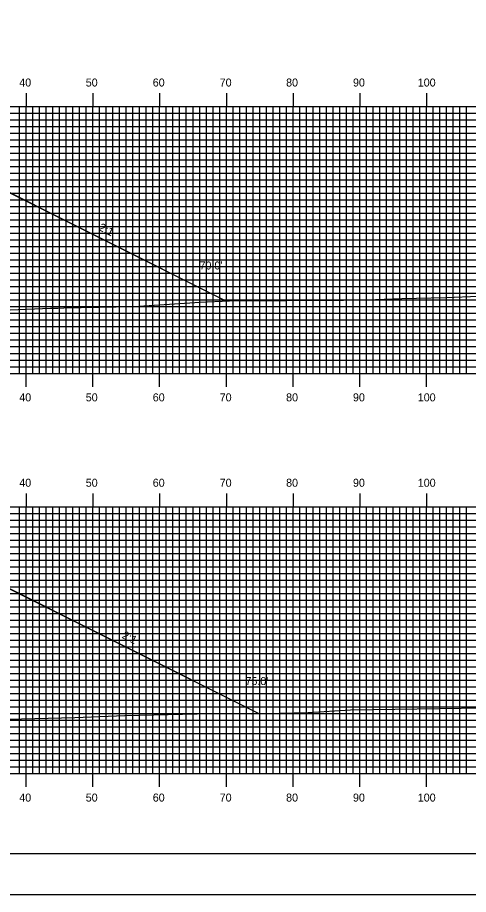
# Model space of a CAD drawing. Extents: x 1759823 to 1760167, y 442591 to 442811.
# Drawn here: x 1760027.9 to 1760095.5, y 442590.5 to 442722 of the extents above; entities that cross this region are included whole.
import ezdxf

# ---------------------------------------------------------------- set-up
doc = ezdxf.new("R2010")
doc.units = 0
for name, color, linetype in [('ANNOTATION', 7, 'Continuous'), ('BORDER', 7, 'Continuous'), ('D_Roadway_Centerline', 7, 'Continuous'), ('D_Roadway_SlopeLines', 7, 'Continuous'), ('D_Text_Standard', 7, 'Continuous'), ('H_V ANNOTATION', 7, 'Continuous'), ('MAJOR', 7, 'Continuous'), ('MINOR', 7, 'Continuous'), ('PLOT BOUNDARY', 7, 'Continuous'), ('S_Roadway_Centerline', 7, 'Continuous')]:
    doc.layers.add(name, color=color, linetype=linetype)

msp = doc.modelspace()

# ---------------------------------------------------------------- linework, layer by layer
at = {"layer": 'BORDER'}
msp.add_lwpolyline([(1759839.59, 442596.67), (1760159.59, 442596.67), (1760159.59, 442806.67), (1759839.59, 442806.67)], close=True, dxfattribs=at)
at = {"layer": 'D_Roadway_Centerline'}
for points in [[(1759922.68, 442675.79), (1759960.89, 442694.9), (1759966.19, 442697.54), (1759969.19, 442697.66), (1759977.19, 442697.98), (1759989.19, 442698.41), (1760001.19, 442698.85), (1760009.8, 442699.16), (1760017.8, 442698.84), (1760020.8, 442698.72), (1760025.55, 442696.34), (1760059.22, 442679.5)], [(1759922.69, 442615.3), (1759960.89, 442634.4), (1759966.19, 442637.04), (1759969.19, 442637.16), (1759977.19, 442637.48), (1759989.19, 442637.91), (1760001.19, 442638.35), (1760011.86, 442638.73), (1760019.86, 442638.41), (1760022.86, 442638.29), (1760027.61, 442635.92), (1760064.16, 442617.64)]]:
    msp.add_lwpolyline(points, dxfattribs=at)
at = {"layer": 'D_Roadway_SlopeLines'}
for points in [[(1760020.8, 442698.72), (1760059.22, 442679.5)], [(1760022.86, 442638.29), (1760064.16, 442617.64)]]:
    msp.add_lwpolyline(points, dxfattribs=at)
at = {"layer": 'MAJOR'}
for p, q in [((1760029.19, 442710.67), (1760029.19, 442708.67)), ((1760039.19, 442710.67), (1760039.19, 442708.67)), ((1760049.19, 442710.67), (1760049.19, 442708.67)), ((1760059.19, 442710.67), (1760059.19, 442708.67)), ((1760069.19, 442710.67), (1760069.19, 442708.67)), ((1760079.19, 442710.67), (1760079.19, 442708.67)), ((1760089.19, 442710.67), (1760089.19, 442708.67)), ((1759849.19, 442708.67), (1760129.19, 442708.67)), ((1759849.19, 442708.67), (1760129.19, 442708.67)), ((1760029.19, 442668.67), (1760029.19, 442708.67)), ((1760039.19, 442668.67), (1760039.19, 442708.67)), ((1760049.19, 442668.67), (1760049.19, 442708.67)), ((1760059.19, 442668.67), (1760059.19, 442708.67)), ((1760069.19, 442668.67), (1760069.19, 442708.67)), ((1760079.19, 442668.67), (1760079.19, 442708.67)), ((1760089.19, 442668.67), (1760089.19, 442708.67)), ((1759849.19, 442703.67), (1760129.19, 442703.67)), ((1759849.19, 442698.67), (1760129.19, 442698.67)), ((1759849.19, 442693.67), (1760129.19, 442693.67)), ((1759849.19, 442688.67), (1760129.19, 442688.67)), ((1759849.19, 442683.67), (1760129.19, 442683.67)), ((1759849.19, 442678.67), (1760129.19, 442678.67)), ((1759849.19, 442673.67), (1760129.19, 442673.67)), ((1759849.19, 442668.67), (1760129.19, 442668.67)), ((1759849.19, 442668.67), (1760129.19, 442668.67)), ((1760029.19, 442666.66), (1760029.19, 442668.67)), ((1760039.19, 442666.66), (1760039.19, 442668.67)), ((1760049.19, 442666.66), (1760049.19, 442668.67)), ((1760059.19, 442666.66), (1760059.19, 442668.67)), ((1760069.19, 442666.66), (1760069.19, 442668.67)), ((1760079.19, 442666.66), (1760079.19, 442668.67)), ((1760089.19, 442666.66), (1760089.19, 442668.67)), ((1760029.19, 442650.67), (1760029.19, 442648.67)), ((1760039.19, 442650.67), (1760039.19, 442648.67)), ((1760049.19, 442650.67), (1760049.19, 442648.67)), ((1760059.19, 442650.67), (1760059.19, 442648.67)), ((1760069.19, 442650.67), (1760069.19, 442648.67)), ((1760079.19, 442650.67), (1760079.19, 442648.67)), ((1760089.19, 442650.67), (1760089.19, 442648.67)), ((1759849.19, 442648.67), (1760129.19, 442648.67)), ((1759849.19, 442648.67), (1760129.19, 442648.67)), ((1760029.19, 442608.67), (1760029.19, 442648.67)), ((1760039.19, 442608.67), (1760039.19, 442648.67)), ((1760049.19, 442608.67), (1760049.19, 442648.67)), ((1760059.19, 442608.67), (1760059.19, 442648.67)), ((1760069.19, 442608.67), (1760069.19, 442648.67)), ((1760079.19, 442608.67), (1760079.19, 442648.67)), ((1760089.19, 442608.67), (1760089.19, 442648.67)), ((1759849.19, 442643.67), (1760129.19, 442643.67)), ((1759849.19, 442638.67), (1760129.19, 442638.67)), ((1759849.19, 442633.67), (1760129.19, 442633.67)), ((1759849.19, 442628.67), (1760129.19, 442628.67)), ((1759849.19, 442623.67), (1760129.19, 442623.67)), ((1759849.19, 442618.67), (1760129.19, 442618.67)), ((1759849.19, 442613.67), (1760129.19, 442613.67)), ((1759849.19, 442608.67), (1760129.19, 442608.67)), ((1759849.19, 442608.67), (1760129.19, 442608.67)), ((1760029.19, 442606.66), (1760029.19, 442608.67)), ((1760039.19, 442606.66), (1760039.19, 442608.67)), ((1760049.19, 442606.66), (1760049.19, 442608.67)), ((1760059.19, 442606.66), (1760059.19, 442608.67)), ((1760069.19, 442606.66), (1760069.19, 442608.67)), ((1760079.19, 442606.66), (1760079.19, 442608.67)), ((1760089.19, 442606.66), (1760089.19, 442608.67))]:
    msp.add_line(p, q, dxfattribs=at)
at = {"layer": 'MINOR'}
for p, q in [((1760028.19, 442668.67), (1760028.19, 442708.67)), ((1760030.19, 442668.67), (1760030.19, 442708.67)), ((1760031.19, 442668.67), (1760031.19, 442708.67)), ((1760032.19, 442668.67), (1760032.19, 442708.67)), ((1760033.19, 442668.67), (1760033.19, 442708.67)), ((1760034.19, 442668.67), (1760034.19, 442708.67)), ((1760035.19, 442668.67), (1760035.19, 442708.67)), ((1760036.19, 442668.67), (1760036.19, 442708.67)), ((1760037.19, 442668.67), (1760037.19, 442708.67)), ((1760038.19, 442668.67), (1760038.19, 442708.67)), ((1760040.19, 442668.67), (1760040.19, 442708.67)), ((1760041.19, 442668.67), (1760041.19, 442708.67)), ((1760042.19, 442668.67), (1760042.19, 442708.67)), ((1760043.19, 442668.67), (1760043.19, 442708.67)), ((1760044.19, 442668.67), (1760044.19, 442708.67)), ((1760045.19, 442668.67), (1760045.19, 442708.67)), ((1760046.19, 442668.67), (1760046.19, 442708.67)), ((1760047.19, 442668.67), (1760047.19, 442708.67)), ((1760048.19, 442668.67), (1760048.19, 442708.67)), ((1760050.19, 442668.67), (1760050.19, 442708.67)), ((1760051.19, 442668.67), (1760051.19, 442708.67)), ((1760052.19, 442668.67), (1760052.19, 442708.67)), ((1760053.19, 442668.67), (1760053.19, 442708.67)), ((1760054.19, 442668.67), (1760054.19, 442708.67)), ((1760055.19, 442668.67), (1760055.19, 442708.67)), ((1760056.19, 442668.67), (1760056.19, 442708.67)), ((1760057.19, 442668.67), (1760057.19, 442708.67)), ((1760058.19, 442668.67), (1760058.19, 442708.67)), ((1760060.19, 442668.67), (1760060.19, 442708.67)), ((1760061.19, 442668.67), (1760061.19, 442708.67)), ((1760062.19, 442668.67), (1760062.19, 442708.67)), ((1760063.19, 442668.67), (1760063.19, 442708.67)), ((1760064.19, 442668.67), (1760064.19, 442708.67)), ((1760065.19, 442668.67), (1760065.19, 442708.67)), ((1760066.19, 442668.67), (1760066.19, 442708.67)), ((1760067.19, 442668.67), (1760067.19, 442708.67)), ((1760068.19, 442668.67), (1760068.19, 442708.67)), ((1760070.19, 442668.67), (1760070.19, 442708.67)), ((1760071.19, 442668.67), (1760071.19, 442708.67)), ((1760072.19, 442668.67), (1760072.19, 442708.67)), ((1760073.19, 442668.67), (1760073.19, 442708.67)), ((1760074.19, 442668.67), (1760074.19, 442708.67)), ((1760075.19, 442668.67), (1760075.19, 442708.67)), ((1760076.19, 442668.67), (1760076.19, 442708.67)), ((1760077.19, 442668.67), (1760077.19, 442708.67)), ((1760078.19, 442668.67), (1760078.19, 442708.67)), ((1760080.19, 442668.67), (1760080.19, 442708.67)), ((1760081.19, 442668.67), (1760081.19, 442708.67)), ((1760082.19, 442668.67), (1760082.19, 442708.67)), ((1760083.19, 442668.67), (1760083.19, 442708.67)), ((1760084.19, 442668.67), (1760084.19, 442708.67)), ((1760085.19, 442668.67), (1760085.19, 442708.67)), ((1760086.19, 442668.67), (1760086.19, 442708.67)), ((1760087.19, 442668.67), (1760087.19, 442708.67)), ((1760088.19, 442668.67), (1760088.19, 442708.67)), ((1760090.19, 442668.67), (1760090.19, 442708.67)), ((1760091.19, 442668.67), (1760091.19, 442708.67)), ((1760092.19, 442668.67), (1760092.19, 442708.67)), ((1760093.19, 442668.67), (1760093.19, 442708.67)), ((1760094.19, 442668.67), (1760094.19, 442708.67)), ((1760095.19, 442668.67), (1760095.19, 442708.67)), ((1759849.19, 442707.67), (1760129.19, 442707.67)), ((1759849.19, 442706.67), (1760129.19, 442706.67)), ((1759849.19, 442705.67), (1760129.19, 442705.67)), ((1759849.19, 442704.67), (1760129.19, 442704.67)), ((1759849.19, 442702.67), (1760129.19, 442702.67)), ((1759849.19, 442701.67), (1760129.19, 442701.67)), ((1759849.19, 442700.67), (1760129.19, 442700.67)), ((1759849.19, 442699.67), (1760129.19, 442699.67)), ((1759849.19, 442697.67), (1760129.19, 442697.67)), ((1759849.19, 442696.67), (1760129.19, 442696.67)), ((1759849.19, 442695.67), (1760129.19, 442695.67)), ((1759849.19, 442694.67), (1760129.19, 442694.67)), ((1759849.19, 442692.67), (1760129.19, 442692.67)), ((1759849.19, 442691.67), (1760129.19, 442691.67)), ((1759849.19, 442690.67), (1760129.19, 442690.67)), ((1759849.19, 442689.67), (1760129.19, 442689.67)), ((1759849.19, 442687.67), (1760129.19, 442687.67)), ((1759849.19, 442686.67), (1760129.19, 442686.67)), ((1759849.19, 442685.67), (1760129.19, 442685.67)), ((1759849.19, 442684.67), (1760129.19, 442684.67)), ((1759849.19, 442682.67), (1760129.19, 442682.67)), ((1759849.19, 442681.67), (1760129.19, 442681.67)), ((1759849.19, 442680.67), (1760129.19, 442680.67)), ((1759849.19, 442679.67), (1760129.19, 442679.67)), ((1759849.19, 442677.67), (1760129.19, 442677.67)), ((1759849.19, 442676.67), (1760129.19, 442676.67)), ((1759849.19, 442675.67), (1760129.19, 442675.67)), ((1759849.19, 442674.67), (1760129.19, 442674.67)), ((1759849.19, 442672.67), (1760129.19, 442672.67)), ((1759849.19, 442671.67), (1760129.19, 442671.67)), ((1759849.19, 442670.67), (1760129.19, 442670.67)), ((1759849.19, 442669.67), (1760129.19, 442669.67)), ((1759849.19, 442647.67), (1760129.19, 442647.67)), ((1760028.19, 442608.67), (1760028.19, 442648.67)), ((1760030.19, 442608.67), (1760030.19, 442648.67)), ((1760031.19, 442608.67), (1760031.19, 442648.67)), ((1760032.19, 442608.67), (1760032.19, 442648.67)), ((1760033.19, 442608.67), (1760033.19, 442648.67)), ((1760034.19, 442608.67), (1760034.19, 442648.67)), ((1760035.19, 442608.67), (1760035.19, 442648.67)), ((1760036.19, 442608.67), (1760036.19, 442648.67)), ((1760037.19, 442608.67), (1760037.19, 442648.67)), ((1760038.19, 442608.67), (1760038.19, 442648.67)), ((1760040.19, 442608.67), (1760040.19, 442648.67)), ((1760041.19, 442608.67), (1760041.19, 442648.67)), ((1760042.19, 442608.67), (1760042.19, 442648.67)), ((1760043.19, 442608.67), (1760043.19, 442648.67)), ((1760044.19, 442608.67), (1760044.19, 442648.67)), ((1760045.19, 442608.67), (1760045.19, 442648.67)), ((1760046.19, 442608.67), (1760046.19, 442648.67)), ((1760047.19, 442608.67), (1760047.19, 442648.67)), ((1760048.19, 442608.67), (1760048.19, 442648.67)), ((1760050.19, 442608.67), (1760050.19, 442648.67)), ((1760051.19, 442608.67), (1760051.19, 442648.67)), ((1760052.19, 442608.67), (1760052.19, 442648.67)), ((1760053.19, 442608.67), (1760053.19, 442648.67)), ((1760054.19, 442608.67), (1760054.19, 442648.67)), ((1760055.19, 442608.67), (1760055.19, 442648.67)), ((1760056.19, 442608.67), (1760056.19, 442648.67)), ((1760057.19, 442608.67), (1760057.19, 442648.67)), ((1760058.19, 442608.67), (1760058.19, 442648.67)), ((1760060.19, 442608.67), (1760060.19, 442648.67)), ((1760061.19, 442608.67), (1760061.19, 442648.67)), ((1760062.19, 442608.67), (1760062.19, 442648.67)), ((1760063.19, 442608.67), (1760063.19, 442648.67)), ((1760064.19, 442608.67), (1760064.19, 442648.67)), ((1760065.19, 442608.67), (1760065.19, 442648.67)), ((1760066.19, 442608.67), (1760066.19, 442648.67)), ((1760067.19, 442608.67), (1760067.19, 442648.67)), ((1760068.19, 442608.67), (1760068.19, 442648.67)), ((1760070.19, 442608.67), (1760070.19, 442648.67)), ((1760071.19, 442608.67), (1760071.19, 442648.67)), ((1760072.19, 442608.67), (1760072.19, 442648.67)), ((1760073.19, 442608.67), (1760073.19, 442648.67)), ((1760074.19, 442608.67), (1760074.19, 442648.67)), ((1760075.19, 442608.67), (1760075.19, 442648.67)), ((1760076.19, 442608.67), (1760076.19, 442648.67)), ((1760077.19, 442608.67), (1760077.19, 442648.67)), ((1760078.19, 442608.67), (1760078.19, 442648.67)), ((1760080.19, 442608.67), (1760080.19, 442648.67)), ((1760081.19, 442608.67), (1760081.19, 442648.67)), ((1760082.19, 442608.67), (1760082.19, 442648.67)), ((1760083.19, 442608.67), (1760083.19, 442648.67)), ((1760084.19, 442608.67), (1760084.19, 442648.67)), ((1760085.19, 442608.67), (1760085.19, 442648.67)), ((1760086.19, 442608.67), (1760086.19, 442648.67)), ((1760087.19, 442608.67), (1760087.19, 442648.67)), ((1760088.19, 442608.67), (1760088.19, 442648.67)), ((1760090.19, 442608.67), (1760090.19, 442648.67)), ((1760091.19, 442608.67), (1760091.19, 442648.67)), ((1760092.19, 442608.67), (1760092.19, 442648.67)), ((1760093.19, 442608.67), (1760093.19, 442648.67)), ((1760094.19, 442608.67), (1760094.19, 442648.67)), ((1760095.19, 442608.67), (1760095.19, 442648.67)), ((1759849.19, 442646.67), (1760129.19, 442646.67)), ((1759849.19, 442645.67), (1760129.19, 442645.67)), ((1759849.19, 442644.67), (1760129.19, 442644.67)), ((1759849.19, 442642.67), (1760129.19, 442642.67)), ((1759849.19, 442641.67), (1760129.19, 442641.67)), ((1759849.19, 442640.67), (1760129.19, 442640.67)), ((1759849.19, 442639.67), (1760129.19, 442639.67)), ((1759849.19, 442637.67), (1760129.19, 442637.67)), ((1759849.19, 442636.67), (1760129.19, 442636.67)), ((1759849.19, 442635.67), (1760129.19, 442635.67)), ((1759849.19, 442634.67), (1760129.19, 442634.67)), ((1759849.19, 442632.67), (1760129.19, 442632.67)), ((1759849.19, 442631.67), (1760129.19, 442631.67)), ((1759849.19, 442630.67), (1760129.19, 442630.67)), ((1759849.19, 442629.67), (1760129.19, 442629.67)), ((1759849.19, 442627.67), (1760129.19, 442627.67)), ((1759849.19, 442626.67), (1760129.19, 442626.67)), ((1759849.19, 442625.67), (1760129.19, 442625.67)), ((1759849.19, 442624.67), (1760129.19, 442624.67)), ((1759849.19, 442622.67), (1760129.19, 442622.67)), ((1759849.19, 442621.67), (1760129.19, 442621.67)), ((1759849.19, 442620.67), (1760129.19, 442620.67)), ((1759849.19, 442619.67), (1760129.19, 442619.67)), ((1759849.19, 442617.67), (1760129.19, 442617.67)), ((1759849.19, 442616.67), (1760129.19, 442616.67)), ((1759849.19, 442615.67), (1760129.19, 442615.67)), ((1759849.19, 442614.67), (1760129.19, 442614.67)), ((1759849.19, 442612.67), (1760129.19, 442612.67)), ((1759849.19, 442611.67), (1760129.19, 442611.67)), ((1759849.19, 442610.67), (1760129.19, 442610.67)), ((1759849.19, 442609.67), (1760129.19, 442609.67))]:
    msp.add_line(p, q, dxfattribs=at)
at = {"layer": 'PLOT BOUNDARY'}
msp.add_lwpolyline([(1759823.4, 442590.55), (1760163.4, 442590.55), (1760163.4, 442810.55), (1759823.4, 442810.55)], close=True, dxfattribs=at)
at = {"layer": 'S_Roadway_Centerline'}
for points in [[(1760021.92, 442677.99), (1760032.85, 442678.42), (1760033.94, 442678.46), (1760034.82, 442678.49), (1760045.31, 442678.69), (1760055.22, 442679.36), (1760059.66, 442679.52), (1760076.74, 442679.65), (1760080.19, 442679.7), (1760085.5, 442679.88), (1760092.06, 442680.03), (1760097.04, 442680.25), (1760111.13, 442680.63), (1760114.9, 442680.71), (1760118.12, 442680.84), (1760129.19, 442680.98)], [(1760018.12, 442616.64), (1760028.47, 442616.89), (1760036.49, 442617.09), (1760044, 442617.36), (1760056.97, 442617.66), (1760063.01, 442617.61), (1760071.47, 442617.83), (1760077.81, 442618.21), (1760097.71, 442618.55), (1760098.53, 442618.52), (1760103.41, 442618.63), (1760119.61, 442619.04), (1760124.83, 442618.99), (1760129.19, 442619.03)]]:
    msp.add_lwpolyline(points, dxfattribs=at)

# ---------------------------------------------------------------- texts
at = {"layer": 'ANNOTATION'}
for p in [(1760039.95, 442690.18), (1760043.44, 442629.04)]:
    msp.add_text('2:1', height=1.2, rotation=333.4349, dxfattribs=at).set_placement(p)
at = {"layer": 'D_Text_Standard'}
for s, p in [("70.0'", (1760055.17, 442684.24)), ("75.0'", (1760062.05, 442621.94))]:
    msp.add_text(s, height=1.2, dxfattribs=at).set_placement(p)
at = {"layer": 'H_V ANNOTATION'}
for s, p in [('40', (1760028.16, 442711.67)), ('50', (1760038.12, 442711.67)), ('60', (1760048.16, 442711.67)), ('70', (1760058.19, 442711.67)), ('80', (1760068.14, 442711.67)), ('90', (1760078.16, 442711.67)), ('100', (1760087.87, 442711.67)), ('40', (1760028.16, 442664.47)), ('50', (1760038.12, 442664.47)), ('60', (1760048.16, 442664.47)), ('70', (1760058.19, 442664.47)), ('80', (1760068.14, 442664.47)), ('90', (1760078.16, 442664.47)), ('100', (1760087.87, 442664.47)), ('40', (1760028.16, 442651.67)), ('50', (1760038.12, 442651.67)), ('60', (1760048.16, 442651.67)), ('70', (1760058.19, 442651.67)), ('80', (1760068.14, 442651.67)), ('90', (1760078.16, 442651.67)), ('100', (1760087.87, 442651.67)), ('40', (1760028.16, 442604.47)), ('50', (1760038.12, 442604.47)), ('60', (1760048.16, 442604.47)), ('70', (1760058.19, 442604.47)), ('80', (1760068.14, 442604.47)), ('90', (1760078.16, 442604.47)), ('100', (1760087.87, 442604.47))]:
    msp.add_text(s, height=1.2, dxfattribs=at).set_placement(p)

doc.saveas('drawing.dxf')
